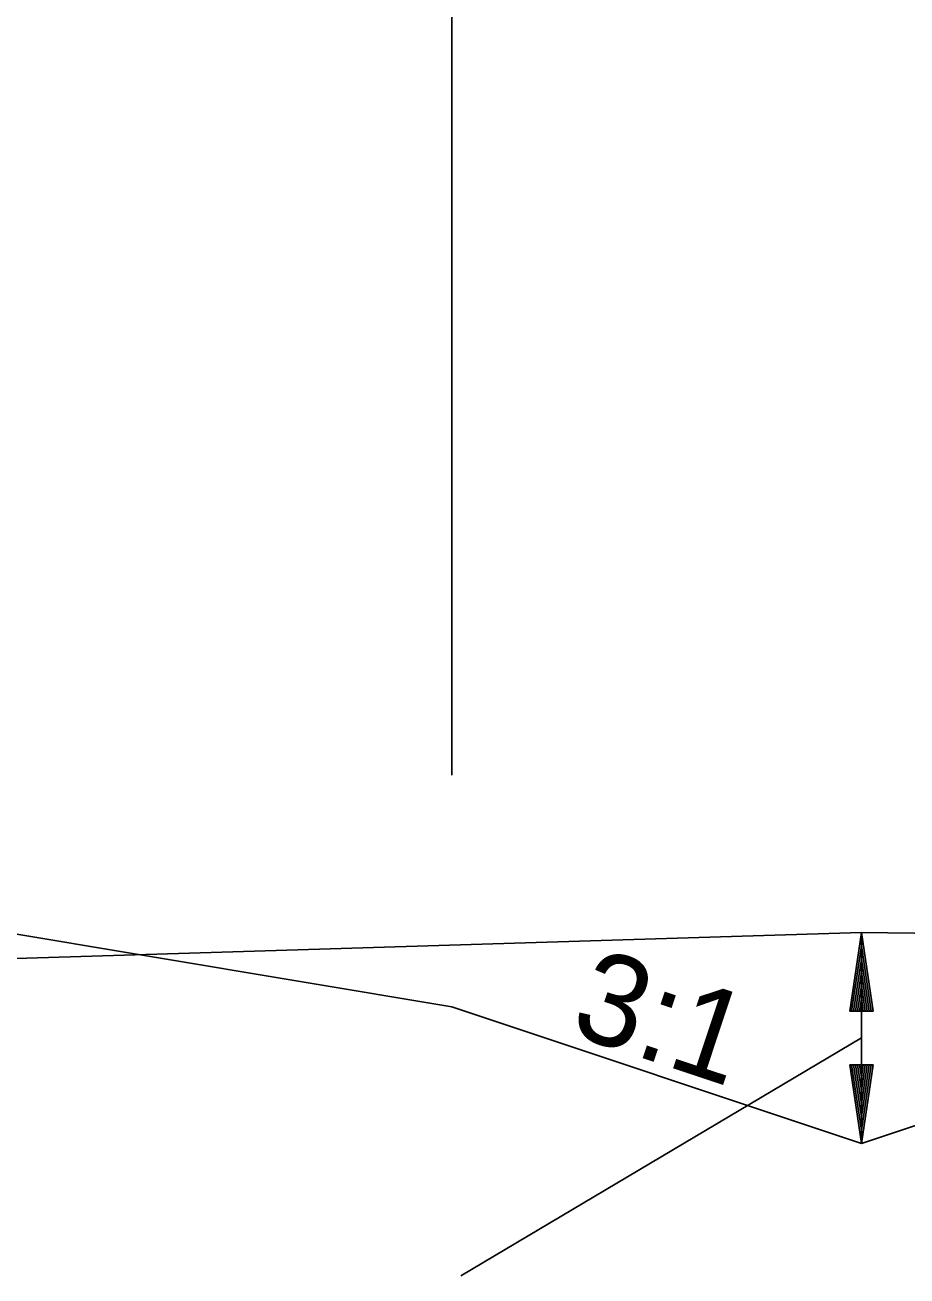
# Model space of a CAD drawing. Extents: x 6848689 to 6848907, y 1900908 to 1901005.
# Drawn here: x 6848768.07 to 6848774.34, y 1900978.34 to 1900987.24 of the extents above; entities that cross this region are included whole.
import ezdxf

# ---------------------------------------------------------------- set-up
doc = ezdxf.new("R2010")
doc.units = 0
for name, color, linetype in [('Default', 7, 'Continuous'), ('R_Draft', 7, 'Continuous'), ('R_No Plot', 7, 'Continuous')]:
    doc.layers.add(name, color=color, linetype=linetype)

msp = doc.modelspace()

# ---------------------------------------------------------------- linework, layer by layer
at = {"layer": 'Default'}
for p, q in [((6848761.0918, 1900981.921), (6848771.104, 1900980.2525)), ((6848774.019, 1900979.2808), (6848778.3541, 1900980.7258)), ((6848774.019, 1900979.2808), (6848771.104, 1900980.2525))]:
    msp.add_line(p, q, dxfattribs=at)
msp.add_lwpolyline([(6848778.3541, 1900980.7258), (6848774.019, 1900980.7808), (6848767.5364, 1900980.5809), (6848765.9191, 1900980.754)], dxfattribs=at)
at = {"layer": 'R_Draft'}
for p, q in [((6848773.9353, 1900980.2222), (6848774.019, 1900980.7808)), ((6848774.1028, 1900980.2222), (6848774.019, 1900980.7808)), ((6848773.9492, 1900980.2222), (6848774.019, 1900980.6875)), ((6848774.0889, 1900980.2222), (6848774.019, 1900980.6875)), ((6848773.9635, 1900980.2222), (6848774.019, 1900980.5914)), ((6848774.0746, 1900980.2222), (6848774.019, 1900980.5914)), ((6848773.9774, 1900980.2222), (6848774.019, 1900980.4984)), ((6848774.0607, 1900980.2222), (6848774.019, 1900980.4984)), ((6848773.992, 1900980.2222), (6848774.019, 1900980.4038)), ((6848774.0464, 1900980.2222), (6848774.019, 1900980.4038)), ((6848774.0059, 1900980.2222), (6848774.019, 1900980.3105)), ((6848774.0322, 1900980.2222), (6848774.019, 1900980.3105)), ((6848773.9353, 1900980.2222), (6848774.1028, 1900980.2222)), ((6848773.9353, 1900979.8393), (6848774.019, 1900979.2808)), ((6848773.9353, 1900979.8393), (6848774.1028, 1900979.8393)), ((6848773.9492, 1900979.8393), (6848774.019, 1900979.3741)), ((6848773.9635, 1900979.8393), (6848774.019, 1900979.4701)), ((6848773.9774, 1900979.8393), (6848774.019, 1900979.5631)), ((6848773.992, 1900979.8393), (6848774.019, 1900979.6578)), ((6848774.0059, 1900979.8393), (6848774.019, 1900979.7511)), ((6848774.1028, 1900979.8393), (6848774.019, 1900979.2808)), ((6848774.0464, 1900979.8393), (6848774.019, 1900979.6578)), ((6848774.0746, 1900979.8393), (6848774.019, 1900979.4701)), ((6848774.0889, 1900979.8393), (6848774.019, 1900979.3741)), ((6848774.0607, 1900979.8393), (6848774.019, 1900979.5631)), ((6848774.0322, 1900979.8393), (6848774.019, 1900979.7511))]:
    msp.add_line(p, q, dxfattribs=at)
at = {"layer": 'R_No Plot'}
for p, q in [((6848771.104, 1900981.9001), (6848771.104, 1900990.4021)), ((6848774.019, 1900979.2808), (6848774.019, 1900980.7808)), ((6848774.019, 1900980.0308), (6848771.169, 1900978.337))]:
    msp.add_line(p, q, dxfattribs=at)

# ---------------------------------------------------------------- texts
at = {"layer": 'R_Draft'}
msp.add_text('3:1', height=0.65, rotation=341.60837, dxfattribs=at).set_placement((6848771.928, 1900980.0645))

doc.saveas('drawing.dxf')
